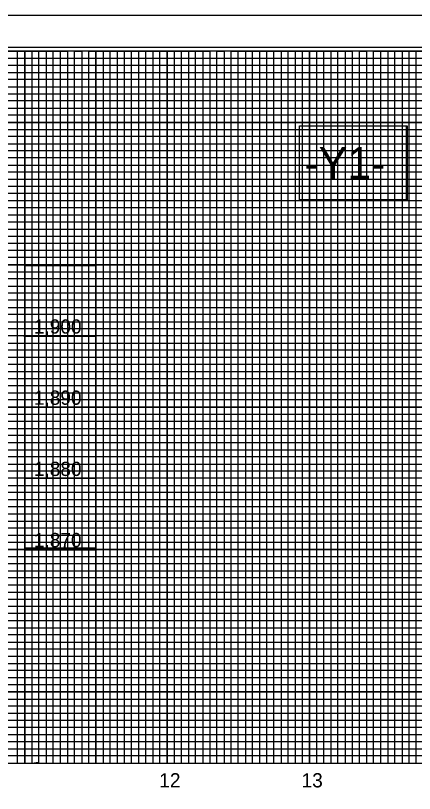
# Model space of a CAD drawing. Extents: x 557032 to 558840, y 515971 to 517218.
# Drawn here: x 558043 to 558323, y 516672 to 517218 of the extents above; entities that cross this region are included whole.
import ezdxf

# ---------------------------------------------------------------- set-up
doc = ezdxf.new("R2010")
doc.units = 0
for name, color, linetype in [('Exist Vertical Profile Horizontal Axis Label Major', 7, 'Continuous'), ('Exist Vertical Profile Vertical Axis Label', 7, 'Continuous'), ('Prop Dimension', 7, 'Continuous'), ('Prop Vertical Profile Curve Label', 7, 'Continuous'), ('Prop Vertical Profile Grade Label', 7, 'Continuous'), ('Prop VPI Label', 7, 'Continuous'), ('Scratch_Level_5', 7, 'Continuous'), ('Sheet Cutting Line CELL', 7, 'Continuous'), ('Sheet DOT Grid CELL', 7, 'Continuous'), ('Sheet Layout Profile Border Port 1', 7, 'Continuous'), ('Sheet Plot Border Inside CELL', 7, 'Continuous'), ('Sheet Plot Border Outside CELL', 7, 'Continuous'), ('Sheet Profile CELL', 7, 'Continuous'), ('Sheet Profile Grid Major CELL', 7, 'Continuous'), ('Sheet Profile Grid Middle CELL', 7, 'Continuous'), ('Sheet Profile Grid Minor CELL', 7, 'Continuous')]:
    doc.layers.add(name, color=color, linetype=linetype)

msp = doc.modelspace()

# ---------------------------------------------------------------- linework, layer by layer
at = {"layer": 'Prop Dimension'}
msp.add_lwpolyline([(558049.45, 517042.65), (558099.45, 517042.65), (558099.45, 516844.15), (558049.45, 516844.15)], close=True, dxfattribs=at)
msp.add_lwpolyline([(558049.45, 517042.65), (558099.45, 517042.65), (558099.45, 516844.15), (558049.45, 516844.15)], close=True, dxfattribs=at)
at = {"layer": 'Prop Vertical Profile Curve Label'}
msp.add_lwpolyline([(558242.5, 517140.65), (558317.26, 517140.65), (558317.26, 517088.71), (558242.5, 517088.71)], close=True, dxfattribs=at)
at = {"layer": 'Prop Vertical Profile Grade Label'}
msp.add_lwpolyline([(558242.5, 517140.65), (558317.94, 517140.65), (558317.94, 517088.77), (558242.5, 517088.77)], close=True, dxfattribs=at)
at = {"layer": 'Prop VPI Label'}
msp.add_lwpolyline([(558242.5, 517140.65), (558317.94, 517140.65), (558317.94, 517088.77), (558242.5, 517088.77)], close=True, dxfattribs=at)
at = {"layer": 'Scratch_Level_5'}
msp.add_lwpolyline([(558499.45, 517193.17), (558099.45, 517193.17), (558099.45, 516693.17), (558649.45, 516693.17), (558649.45, 517032.12), (558499.45, 517032.12)], close=True, dxfattribs=at)
at = {"layer": 'Sheet Cutting Line CELL'}
msp.add_line((558716.45, 517218.17), (557032.45, 517218.17), dxfattribs=at)
at = {"layer": 'Sheet DOT Grid CELL'}
for p, q in [((558049.45, 516693.17), (558049.45, 517193.17)), ((558099.45, 516693.17), (558099.45, 517193.17)), ((558149.45, 516693.17), (558149.45, 517193.17)), ((558199.45, 516693.17), (558199.45, 517193.17)), ((558249.45, 516693.17), (558249.45, 517193.17)), ((558299.45, 516693.17), (558299.45, 517193.17)), ((558499.4, 517143.17), (557199.45, 517143.17)), ((558499.4, 517093.17), (557199.45, 517093.17)), ((558499.45, 517043.17), (557199.45, 517043.17)), ((558699.45, 516993.17), (557199.45, 516993.17)), ((558699.45, 516943.17), (557199.45, 516943.17)), ((558699.45, 516893.17), (557199.45, 516893.17)), ((558699.45, 516843.17), (557199.45, 516843.17)), ((558699.45, 516793.17), (557199.45, 516793.17)), ((558699.45, 516743.17), (557199.45, 516743.17))]:
    msp.add_line(p, q, dxfattribs=at)
at = {"layer": 'Sheet Layout Profile Border Port 1'}
msp.add_lwpolyline([(557249.45, 517032.12), (557249.45, 516693.17), (558649.45, 516693.17), (558649.45, 517032.12)], dxfattribs=at)
at = {"layer": 'Sheet Plot Border Inside CELL'}
msp.add_lwpolyline([(557045.45, 516140.62), (558711.95, 516140.62), (558711.95, 517195.72), (557045.45, 517195.72)], close=True, dxfattribs=at)
at = {"layer": 'Sheet Plot Border Outside CELL'}
msp.add_lwpolyline([(557032.45, 516118.17), (558716.45, 516118.17), (558716.45, 517218.17), (557032.45, 517218.17)], close=True, dxfattribs=at)
at = {"layer": 'Sheet Profile CELL'}
msp.add_line((557199.45, 516693.17), (558699.45, 516693.17), dxfattribs=at)
msp.add_lwpolyline([(558699.45, 517193.17), (557199.45, 517193.17), (557199.45, 516143.17), (558699.45, 516143.17)], close=True, dxfattribs=at)
at = {"layer": 'Sheet Profile Grid Major CELL'}
for p, q in [((558048.8, 516993.02), (558099.4, 516993.02)), ((558049.45, 516993.02), (558099.45, 516993.02)), ((558099.45, 516943.12), (558049.45, 516943.17)), ((558049.45, 516943.17), (558099.45, 516943.17)), ((558099.45, 516893.17), (558049.45, 516893.17)), ((558049.45, 516893.17), (558099.45, 516893.17))]:
    msp.add_line(p, q, dxfattribs=at)
for points in [[(557999.45, 517193.17), (558049.45, 517193.17), (558049.45, 516842.99), (558099.45, 516842.99), (558099.45, 517193.17), (558149.45, 517193.17), (558149.45, 516693.17), (558199.45, 516693.17), (558199.45, 517193.17), (558249.45, 517193.17), (558249.45, 516693.17), (558299.45, 516693.17), (558299.45, 517193.17), (558349.45, 517193.17), (558349.45, 516693.17), (558399.45, 516693.17), (558399.45, 517193.17), (558449.45, 517193.17), (558449.45, 516693.17), (558499.45, 516693.17), (558499.45, 517193.17), (558525.75, 517193.17)], [(557199.45, 517143.17), (558499.45, 517143.17)], [(558499.45, 517093.17), (557199.45, 517093.17), (557199.45, 517043.17), (558499.45, 517043.17)], [(558699.45, 516993.17), (557199.45, 516993.17), (557199.45, 516943.17), (558699.45, 516943.17)], [(558699.45, 516893.17), (557199.45, 516893.17), (557199.45, 516843.17), (558699.45, 516843.17)], [(558699.45, 516793.17), (557199.45, 516793.17), (557199.45, 516793.17), (557199.45, 516743.17), (558699.45, 516743.17)]]:
    msp.add_lwpolyline(points, dxfattribs=at)
at = {"layer": 'Sheet Profile Grid Middle CELL'}
msp.add_line((557199.45, 517168.17), (558499.4, 517168.17), dxfattribs=at)
for points in [[(558024.45, 517193.17), (558074.45, 517193.17), (558074.45, 516693.17), (558124.45, 516693.17), (558124.45, 517193.17), (558174.45, 517193.17), (558174.45, 516693.17), (558224.45, 516693.17), (558224.45, 517193.17), (558274.45, 517193.17), (558274.45, 516693.17), (558324.45, 516693.17), (558324.45, 517193.17), (558374.45, 517193.17), (558374.45, 516693.17), (558424.45, 516693.17), (558424.45, 517193.17), (558474.45, 517193.17), (558474.45, 516693.17), (558524.45, 516693.17), (558524.45, 517032.12)], [(558499.45, 517118.17), (557199.45, 517118.17), (557199.45, 517068.17), (558499.45, 517068.17)], [(558699.45, 517018.17), (557199.45, 517018.17), (557199.45, 516968.17), (558524.45, 516968.17)], [(558699.45, 516918.17), (557199.45, 516918.17), (557199.45, 516868.17), (558699.45, 516868.17)], [(558699.45, 516818.17), (557199.45, 516818.17), (557199.45, 516768.17), (558699.45, 516768.17)], [(558699.45, 516718.17), (557199.45, 516718.17)]]:
    msp.add_lwpolyline(points, dxfattribs=at)
at = {"layer": 'Sheet Profile Grid Minor CELL'}
for p, q in [((558049.45, 517193.17), (558049.45, 516693.17)), ((558099.45, 516693.17), (558099.45, 517193.17)), ((557249.45, 517188.17), (558499.45, 517188.17)), ((558499.45, 517183.17), (557249.45, 517182.82)), ((557249.45, 517178.17), (558499.45, 517178.17)), ((558499.4, 517058.17), (557249.45, 517058.17)), ((558499.45, 517053.17), (557249.45, 517053.17)), ((558499.45, 517048.17), (557249.45, 517048.17)), ((557249.45, 517038.17), (558499.45, 517038.17)), ((558499.45, 517033.17), (557249.45, 517033.17)), ((557249.45, 517028.17), (558649.45, 517028.17)), ((558649.45, 517008.17), (557249.45, 517008.17)), ((557249.45, 517003.17), (558649.45, 517003.17)), ((558649.45, 516983.17), (557249.45, 516983.17)), ((557249.45, 516978.17), (558649.45, 516978.17)), ((558649.45, 516958.17), (557249.45, 516958.17)), ((557249.45, 516953.17), (558649.45, 516953.17)), ((558649.45, 516948.17), (557249.45, 516948.17)), ((557249.45, 516938.17), (558649.45, 516938.17)), ((558649.45, 516933.17), (557249.45, 516933.17)), ((557249.45, 516928.17), (558649.45, 516928.17)), ((558649.45, 516923.17), (557249.45, 516923.17)), ((557249.45, 516913.17), (558649.45, 516913.17)), ((558649.45, 516908.17), (557249.45, 516908.17)), ((557249.45, 516903.17), (558649.45, 516903.17)), ((558649.45, 516898.17), (557249.45, 516898.17)), ((557249.45, 516888.17), (558649.45, 516888.17)), ((558649.45, 516883.17), (557249.45, 516883.17)), ((557249.45, 516878.17), (558649.45, 516878.17)), ((558649.45, 516873.17), (557249.45, 516873.17)), ((557249.45, 516863.17), (558649.45, 516863.17)), ((558649.45, 516858.17), (557249.45, 516858.17)), ((557249.45, 516853.17), (558649.45, 516853.17)), ((558649.45, 516848.17), (557249.45, 516848.17)), ((557249.45, 516838.17), (558649.45, 516838.17)), ((558649.45, 516833.17), (557249.45, 516833.17)), ((557249.45, 516828.17), (558649.45, 516828.17)), ((558649.45, 516823.17), (557249.45, 516823.17)), ((557249.45, 516813.17), (558649.45, 516813.17)), ((558649.45, 516808.17), (557249.45, 516808.17)), ((558649.45, 516803.17), (557249.45, 516803.17)), ((558649.45, 516798.17), (557249.45, 516798.17)), ((557249.45, 516788.17), (558649.45, 516788.17)), ((558649.45, 516783.17), (557249.45, 516783.17)), ((557249.45, 516778.17), (558649.45, 516778.17)), ((558649.45, 516773.17), (557249.45, 516773.17)), ((557249.45, 516763.17), (558649.45, 516763.17)), ((558649.45, 516758.17), (557249.45, 516758.17)), ((557249.45, 516753.17), (558649.45, 516753.17)), ((558649.45, 516748.17), (557249.45, 516748.17)), ((557249.45, 516738.17), (558649.45, 516738.17)), ((558649.45, 516733.17), (557249.45, 516733.17)), ((557249.45, 516728.17), (558649.45, 516728.17)), ((558649.45, 516723.17), (557249.45, 516723.17)), ((557249.45, 516713.17), (558649.45, 516713.17)), ((558649.45, 516708.17), (557249.45, 516708.17)), ((557249.45, 516703.17), (558649.45, 516703.17))]:
    msp.add_line(p, q, dxfattribs=at)
for points in [[(558039.45, 516693.17), (558044.45, 516693.17), (558044.45, 517193.17), (558054.45, 517193.17), (558054.45, 516693.17), (558059.15, 516693.72), (558059.45, 516693.17), (558059.45, 517193.17), (558064.45, 517193.17), (558064.45, 516693.17), (558069.45, 516693.17), (558069.45, 517193.17), (558079.45, 517193.17), (558079.45, 516693.17), (558084.45, 516693.17)], [(558084.45, 516693.17), (558084.45, 517193.17), (558089.45, 517193.17), (558089.45, 516693.17), (558094.45, 516693.17), (558094.45, 517193.17), (558104.45, 517193.17), (558104.45, 516693.17), (558109.45, 516693.17), (558109.45, 517193.17), (558114.45, 517193.17), (558114.45, 516693.17), (558119.45, 516693.17), (558119.45, 517193.17), (558129.45, 517193.17), (558129.45, 516693.17), (558134.45, 516693.17), (558134.45, 517193.17), (558139.45, 517193.17), (558139.45, 516693.17), (558144.45, 516693.17), (558144.45, 517193.17), (558154.45, 517193.17), (558154.45, 516693.17), (558159.45, 516693.17), (558159.45, 517193.17), (558164.45, 517193.17), (558164.45, 516693.17), (558169.45, 516693.17), (558169.45, 517193.17), (558179.45, 517193.17), (558179.45, 516693.17), (558184.45, 516693.17), (558184.45, 517193.17), (558189.45, 517193.17), (558189.45, 516693.17), (558194.45, 516693.17), (558194.45, 517193.17), (558204.45, 517193.17), (558204.45, 516693.17), (558209.45, 516693.17), (558209.45, 517193.17), (558214.45, 517193.17), (558214.45, 516693.17), (558219.45, 516693.17), (558219.45, 517193.17), (558229.45, 517193.17), (558229.45, 516693.17), (558234.45, 516693.17), (558234.45, 517193.17), (558239.45, 517193.17), (558239.45, 516693.17), (558244.45, 516693.17), (558244.45, 517193.17), (558254.45, 517193.17), (558254.45, 516693.17), (558259.45, 516693.17), (558259.45, 517193.17), (558264.45, 517193.17), (558264.45, 516693.17), (558269.45, 516693.17), (558269.45, 517193.17), (558279.45, 517193.17), (558279.45, 516693.17), (558284.45, 516693.17), (558284.45, 517193.17), (558289.45, 517193.17), (558289.45, 516693.17), (558294.45, 516693.17), (558294.45, 517193.17), (558304.45, 517193.17), (558304.45, 516693.17), (558309.45, 516693.17), (558309.45, 517193.17), (558314.45, 517193.17), (558314.45, 516693.17), (558319.45, 516693.17), (558319.45, 517193.17), (558329.45, 517193.17)], [(558499.45, 517173.17), (557249.45, 517173.17), (557249.45, 517163.17), (558499.45, 517163.17)], [(558499.4, 517158.17), (557249.45, 517158.17), (557249.45, 517153.17), (558499.45, 517153.17)], [(558499.45, 517148.17), (557249.45, 517148.17), (557249.45, 517138.17), (558499.45, 517138.17)], [(558499.45, 517133.17), (557249.45, 517133.17), (557249.45, 517128.17), (558499.45, 517128.17)], [(558499.45, 517123.17), (557249.45, 517123.17), (557249.45, 517113.17), (558499.45, 517113.17)], [(558499.45, 517108.17), (557249.45, 517108.17), (557249.45, 517103.17), (558499.45, 517103.17)], [(558499.45, 517098.17), (557249.45, 517098.17), (557249.45, 517088.17), (558499.45, 517088.17)], [(558499.45, 517083.07), (557249.55, 517083.07), (557249.55, 517078.17), (558499.45, 517078.17)], [(558499.45, 517073.17), (557249.45, 517073.17), (557249.45, 517063.17), (558499.45, 517063.17)], [(558649.45, 517023.17), (557249.45, 517023.17), (557249.45, 517013.17), (558649.45, 517013.17)], [(558649.45, 516998.17), (557249.45, 516998.17), (557249.45, 516988.17), (558649.45, 516988.17)], [(558649.45, 516973.17), (557249.45, 516973.17), (557249.45, 516963.17), (558649.45, 516963.17)], [(558649.45, 516698.17), (557249.45, 516698.17)]]:
    msp.add_lwpolyline(points, dxfattribs=at)

# ---------------------------------------------------------------- texts
at = {"layer": 'Exist Vertical Profile Horizontal Axis Label Major'}
for s, p in [('12', (558143.97, 516676.08)), ('13', (558243.9, 516676.08))]:
    msp.add_text(s, height=10, dxfattribs=at).set_placement(p)
at = {"layer": 'Exist Vertical Profile Vertical Axis Label'}
for s, p in [('1,900', (558055.91, 516994.8)), ('1,890', (558055.91, 516944.8)), ('1,880', (558055.91, 516894.8)), ('1,870', (558055.91, 516844.8))]:
    msp.add_text(s, height=10, dxfattribs=at).set_placement(p)
at = {"layer": 'Prop Vertical Profile Grade Label'}
msp.add_text('-Y1-', height=22.5, dxfattribs=at).set_placement((558245.88, 517103.29))

doc.saveas('drawing.dxf')
